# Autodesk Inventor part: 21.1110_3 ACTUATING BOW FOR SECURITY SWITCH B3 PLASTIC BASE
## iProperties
Created: 2007-05
Part Number: 21.1110_3 ACTUATING BOW FOR SECURITY SWITCH B3 PLASTIC BASE
Material: ABS Plastic
Document SubType Name: Modeling
Designer: Andy Moles
Density: 1.06 g/cm^3
Author: Andy Moles
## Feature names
1. Extrusion1
2. Chamfer1
3. Extrusion2
4. Extrusion3
5. Extrusion4
